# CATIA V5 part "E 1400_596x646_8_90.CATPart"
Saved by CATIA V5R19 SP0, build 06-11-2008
Definition: E 1400_596x646_8_90
Nomenclature: E 1400_596x646_8_90
Description: PART--DESC
Material "Epoxy": density 1300 kg/m3, Young's modulus 3e+09 Pa, Poisson ratio 0.37, thermal expansion 6e-05 1/K
Bounding box of the stored display mesh (mm): x -323 to 323, y -298 to 298, z 142 to 150
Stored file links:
  G:\UTB\Kombinované\Bakalářská práce\Catia\FORMA\E 1400_596x646_8_90.CATPart
  D:\Aplikace\CATIA\Nová složka\win_b64\startup\materials\Catalog.CATMaterial
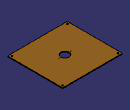
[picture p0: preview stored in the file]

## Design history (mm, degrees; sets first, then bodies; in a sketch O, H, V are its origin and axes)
Body1 "E 1400_596 646_8_90" (main body)
  Solid1: solid without history
  Sketch1 on face of Solid1, origin (0, 0, 150), H (1, 0, 0), V (0, 1, 0)
    point P1 (0, 0)
    construction line L1 (300, 275) -> (300, -275)
    construction line L2 (300, -275) -> (-300, -275)
    construction line L3 (-300, -275) -> (-300, 275)
    construction line L4 (-300, 275) -> (300, 275)
    point P4 (-300, -275)
    reference intersected line E1 through (0, 0) direction (-1, 0) from zx-plane
    reference intersected line E2 through (0, 0) direction (0, 1) from yz-plane
    distance L4 L2 = 550
    distance L1 L3 = 600
    vertical: L1 V, L3 V
    horizontal: L2 H, L4 H
    equidistance: L1 L3 P1, L2 L4 P1
    coincidence: P1 E1, P1 E2
  Sketch2 on face of Solid1, origin (-300, -275, 150), H (1, 0, 0), V (0, 1, 0)
    point P1 (0, 0)
    reference projected point E1 (0, 0) from Sketch1.P4
    coincidence: E1 P1
  Hole1: placed by Sketch2, at (-300, -275, 150) direction (0, 0, -1), diameter 9, through (limit type 3), countersink depth 4.28, countersink angle 90
  UserPattern1: of Hole1, copies 4, at the points of Sketch1
  Sketch3 on face of Solid1, origin (-54.3226, 11.5957, 150), H (1, 0, 0), V (0, 1, 0)
    point P1 (-9.6774, -11.5957)
    reference intersected line E1 through (0, -11.5957) direction (-1, 0) from Plane1
    reference intersected line E2 through (54.3226, 0) direction (0, 1) from Plane2
    distance P1 E2 = 64
    coincidence: P1 E1
  Hole2: placed by Sketch3, at (-64, 0, 150) direction (0, 0, -1), diameter 5.5, through (limit type 3)
  CircPattern1: of Hole2, instances 2, angular step 180, axis from face of Solid1
  Plane1: stored without definition
  Plane2: stored without definition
